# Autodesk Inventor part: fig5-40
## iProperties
Created: 2004-05
Part Number: fig5-40
Document SubType Name: Modeling
Designer: CADCIM Technologies
Manufacturer: Standard
Standards Organization: Custom
Author: CADCIM Technologies
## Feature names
1. Extrusion1
2. Extrusion2
3. Fillet1
4. Hole1
5. Fillet2
6. Mirror1
7. Mirror2
